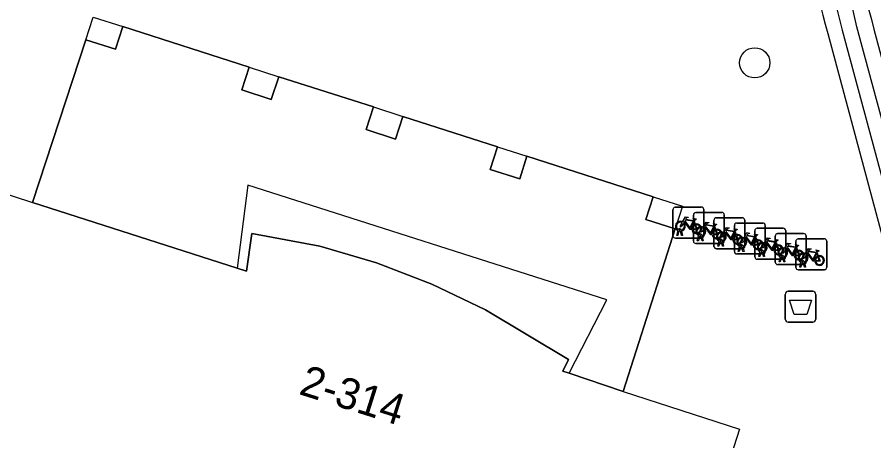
# Model space of a CAD drawing. Extents: x 160676 to 161153, y 383244 to 383713.
# Drawn here: x 161050.01 to 161077.72, y 383266.35 to 383280.05 of the extents above; entities that cross this region are included whole.
import ezdxf

# ---------------------------------------------------------------- set-up
doc = ezdxf.new("R2010")
doc.units = 0
for name, color, linetype in [('IMGEO_Afvalbak', 7, 'Continuous'), ('IMGEO_Boom', 7, 'Continuous'), ('IMGEO_Fietsenrek', 7, 'Continuous'), ('IMGEO_Pand', 7, 'Continuous'), ('IMGEO_Pand_nummerreeks', 7, 'Continuous'), ('IMGEO_Pand_overbouw', 7, 'Continuous'), ('IMGEO_Voetpad_open', 7, 'Continuous')]:
    doc.layers.add(name, color=color, linetype=linetype)

msp = doc.modelspace()

# ---------------------------------------------------------------- linework, layer by layer
at = {"layer": 'IMGEO_Afvalbak'}
for p, q in [((161074.848, 383270.288), (161074.848, 383271.088)), ((161074.848, 383271.088), (161074.848, 383270.288)), ((161074.948, 383271.188), (161075.738, 383271.188)), ((161075.738, 383271.188), (161074.948, 383271.188)), ((161075.838, 383271.088), (161075.838, 383270.288)), ((161075.838, 383270.288), (161075.838, 383271.088)), ((161075.738, 383270.188), (161074.948, 383270.188)), ((161074.948, 383270.188), (161075.738, 383270.188))]:
    msp.add_line(p, q, dxfattribs=at)
msp.add_lwpolyline([(161074.991, 383270.902), (161075.695, 383270.902), (161075.546, 383270.432), (161075.14, 383270.432), (161074.991, 383270.902)], dxfattribs=at)
for centre, start, end in [((161074.948, 383271.088), 90, 180), ((161074.948, 383271.088), 90, 180), ((161075.738, 383271.088), 0, 90), ((161075.738, 383271.088), 360, 90), ((161074.948, 383270.288), 180, 270), ((161074.948, 383270.288), 180, 270), ((161075.738, 383270.288), 270, 0), ((161075.738, 383270.288), 270, 0)]:
    msp.add_arc(centre, 0.1, start, end, dxfattribs=at)
at = {"layer": 'IMGEO_Boom'}
msp.add_circle((161073.864, 383278.575), 0.489, dxfattribs=at)
at = {"layer": 'IMGEO_Fietsenrek'}
for p, q in [((161071.219, 383272.982), (161071.219, 383273.823)), ((161071.219, 383273.823), (161071.219, 383272.982)), ((161071.294, 383273.907), (161072.135, 383273.907)), ((161072.135, 383273.907), (161071.294, 383273.907)), ((161072.219, 383273.832), (161072.219, 383272.991)), ((161072.219, 383272.991), (161072.219, 383273.832)), ((161071.881, 383272.811), (161071.881, 383273.652)), ((161071.881, 383273.652), (161071.881, 383272.811)), ((161071.956, 383273.736), (161072.797, 383273.736)), ((161072.797, 383273.736), (161071.956, 383273.736)), ((161072.618, 383273.566), (161073.459, 383273.566)), ((161073.459, 383273.566), (161072.618, 383273.566)), ((161072.881, 383273.661), (161072.881, 383272.82)), ((161072.881, 383272.82), (161072.881, 383273.661)), ((161071.906, 383273.456), (161071.942, 383273.361)), ((161072.543, 383272.641), (161072.543, 383273.482)), ((161072.543, 383273.482), (161072.543, 383272.641)), ((161072.568, 383273.285), (161072.604, 383273.19)), ((161073.205, 383272.47), (161073.205, 383273.311)), ((161073.205, 383273.311), (161073.205, 383272.47)), ((161073.28, 383273.395), (161074.121, 383273.395)), ((161074.121, 383273.395), (161073.28, 383273.395)), ((161073.543, 383273.491), (161073.543, 383272.65)), ((161073.543, 383272.65), (161073.543, 383273.491)), ((161074.205, 383273.32), (161074.205, 383272.479)), ((161074.205, 383272.479), (161074.205, 383273.32)), ((161071.346, 383272.991), (161071.385, 383273.151)), ((161071.38, 383272.991), (161071.346, 383272.991)), ((161071.415, 383273.139), (161071.38, 383272.991)), ((161071.457, 383273.163), (161071.456, 383273.167)), ((161071.498, 383272.991), (161071.464, 383273.133)), ((161071.488, 383273.174), (161071.489, 383273.167)), ((161071.496, 383273.137), (161071.531, 383272.991)), ((161071.531, 383272.991), (161071.498, 383272.991)), ((161072.008, 383272.82), (161072.047, 383272.98)), ((161072.077, 383272.968), (161072.042, 383272.82)), ((161072.119, 383272.992), (161072.118, 383272.996)), ((161072.15, 383273.003), (161072.151, 383272.996)), ((161073.23, 383273.115), (161073.266, 383273.02)), ((161073.867, 383272.3), (161073.867, 383273.141)), ((161073.867, 383273.141), (161073.867, 383272.3)), ((161073.942, 383273.225), (161074.783, 383273.225)), ((161074.783, 383273.225), (161073.942, 383273.225)), ((161074.529, 383272.129), (161074.529, 383272.97)), ((161074.529, 383272.97), (161074.529, 383272.129)), ((161074.604, 383273.054), (161075.445, 383273.054)), ((161075.445, 383273.054), (161074.604, 383273.054)), ((161074.867, 383273.15), (161074.867, 383272.309)), ((161074.867, 383272.309), (161074.867, 383273.15)), ((161075.529, 383272.979), (161075.529, 383272.138)), ((161075.529, 383272.138), (161075.529, 383272.979)), ((161072.144, 383272.907), (161071.303, 383272.907)), ((161071.303, 383272.907), (161072.144, 383272.907)), ((161072.806, 383272.736), (161071.965, 383272.736)), ((161071.965, 383272.736), (161072.806, 383272.736)), ((161072.042, 383272.82), (161072.008, 383272.82)), ((161072.16, 383272.82), (161072.126, 383272.962)), ((161072.158, 383272.966), (161072.193, 383272.82)), ((161072.193, 383272.82), (161072.16, 383272.82)), ((161072.67, 383272.65), (161072.709, 383272.81)), ((161072.739, 383272.798), (161072.704, 383272.65)), ((161072.781, 383272.822), (161072.78, 383272.826)), ((161072.822, 383272.65), (161072.788, 383272.792)), ((161072.812, 383272.833), (161072.813, 383272.826)), ((161072.82, 383272.796), (161072.855, 383272.65)), ((161073.892, 383272.944), (161073.928, 383272.849)), ((161074.554, 383272.774), (161074.59, 383272.679)), ((161075.191, 383271.958), (161075.191, 383272.799)), ((161075.191, 383272.799), (161075.191, 383271.958)), ((161075.266, 383272.883), (161076.107, 383272.883)), ((161076.107, 383272.883), (161075.266, 383272.883)), ((161076.191, 383272.808), (161076.191, 383271.967)), ((161076.191, 383271.967), (161076.191, 383272.808)), ((161073.468, 383272.566), (161072.627, 383272.566)), ((161072.627, 383272.566), (161073.468, 383272.566)), ((161072.704, 383272.65), (161072.67, 383272.65)), ((161072.855, 383272.65), (161072.822, 383272.65)), ((161073.332, 383272.479), (161073.371, 383272.639)), ((161073.366, 383272.479), (161073.332, 383272.479)), ((161073.401, 383272.627), (161073.366, 383272.479)), ((161073.443, 383272.651), (161073.442, 383272.655)), ((161073.484, 383272.479), (161073.45, 383272.621)), ((161073.474, 383272.662), (161073.475, 383272.655)), ((161073.482, 383272.625), (161073.517, 383272.479)), ((161073.517, 383272.479), (161073.484, 383272.479)), ((161073.994, 383272.309), (161074.033, 383272.469)), ((161074.063, 383272.457), (161074.028, 383272.309)), ((161074.105, 383272.481), (161074.104, 383272.485)), ((161074.146, 383272.309), (161074.112, 383272.451)), ((161074.136, 383272.492), (161074.137, 383272.485)), ((161074.144, 383272.455), (161074.179, 383272.309)), ((161075.216, 383272.603), (161075.252, 383272.508)), ((161075.878, 383272.432), (161075.914, 383272.337)), ((161074.13, 383272.395), (161073.289, 383272.395)), ((161073.289, 383272.395), (161074.13, 383272.395)), ((161074.792, 383272.225), (161073.951, 383272.225)), ((161073.951, 383272.225), (161074.792, 383272.225)), ((161074.028, 383272.309), (161073.994, 383272.309)), ((161074.179, 383272.309), (161074.146, 383272.309)), ((161074.656, 383272.138), (161074.695, 383272.298)), ((161074.69, 383272.138), (161074.656, 383272.138)), ((161074.725, 383272.286), (161074.69, 383272.138)), ((161074.767, 383272.31), (161074.766, 383272.314)), ((161074.808, 383272.138), (161074.774, 383272.28)), ((161074.798, 383272.321), (161074.799, 383272.314)), ((161074.806, 383272.284), (161074.841, 383272.138)), ((161074.841, 383272.138), (161074.808, 383272.138)), ((161075.429, 383272.139), (161075.428, 383272.143)), ((161075.46, 383272.15), (161075.461, 383272.143)), ((161075.454, 383272.054), (161074.613, 383272.054)), ((161074.613, 383272.054), (161075.454, 383272.054)), ((161076.116, 383271.883), (161075.275, 383271.883)), ((161075.275, 383271.883), (161076.116, 383271.883)), ((161075.318, 383271.967), (161075.357, 383272.127)), ((161075.352, 383271.967), (161075.318, 383271.967)), ((161075.387, 383272.115), (161075.352, 383271.967)), ((161075.47, 383271.967), (161075.436, 383272.109)), ((161075.468, 383272.113), (161075.503, 383271.967)), ((161075.503, 383271.967), (161075.47, 383271.967))]:
    msp.add_line(p, q, dxfattribs=at)
for points in [[(161071.532, 383273.433), (161071.627, 383273.597), (161071.713, 383273.583), (161071.715, 383273.574), (161071.659, 383273.563), (161071.632, 383273.518), (161071.888, 383273.477)], [(161071.888, 383273.477), (161071.913, 383273.526), (161071.907, 383273.53), (161071.884, 383273.534), (161071.872, 383273.541), (161071.871, 383273.544), (161071.873, 383273.549), (161071.968, 383273.534), (161071.97, 383273.524), (161071.96, 383273.511), (161071.948, 383273.505), (161071.934, 383273.511), (161071.906, 383273.456)], [(161071.553, 383273.381), (161071.501, 383273.291), (161071.461, 383273.266), (161071.462, 383273.313), (161071.517, 383273.407)], [(161071.828, 383273.189), (161071.778, 383273.189), (161071.587, 383273.44), (161071.568, 383273.408)], [(161071.875, 383273.452), (161071.618, 383273.493), (161071.601, 383273.464), (161071.768, 383273.244), (161071.875, 383273.452)], [(161071.923, 383273.354), (161071.893, 383273.431), (161071.784, 383273.213), (161071.827, 383273.213)], [(161071.857, 383273.213), (161071.977, 383273.212), (161071.933, 383273.326)], [(161071.953, 383273.333), (161072.008, 383273.188), (161071.858, 383273.188)], [(161072.194, 383273.262), (161072.289, 383273.426), (161072.375, 383273.412), (161072.377, 383273.403), (161072.321, 383273.392), (161072.294, 383273.347), (161072.55, 383273.306)], [(161072.49, 383273.018), (161072.44, 383273.018), (161072.249, 383273.269), (161072.23, 383273.237)], [(161072.537, 383273.281), (161072.28, 383273.322), (161072.263, 383273.293), (161072.43, 383273.073), (161072.537, 383273.281)], [(161072.585, 383273.183), (161072.555, 383273.26), (161072.446, 383273.042), (161072.489, 383273.042)], [(161072.55, 383273.306), (161072.575, 383273.355), (161072.569, 383273.359), (161072.546, 383273.363), (161072.534, 383273.37), (161072.533, 383273.373), (161072.535, 383273.378), (161072.63, 383273.363), (161072.632, 383273.353), (161072.622, 383273.34), (161072.61, 383273.334), (161072.596, 383273.34), (161072.568, 383273.285)], [(161072.856, 383273.092), (161072.951, 383273.256), (161073.037, 383273.242), (161073.039, 383273.233), (161072.983, 383273.222), (161072.956, 383273.177), (161073.212, 383273.136)], [(161072.215, 383273.21), (161072.163, 383273.12), (161072.123, 383273.095), (161072.124, 383273.142), (161072.179, 383273.236)], [(161072.519, 383273.042), (161072.639, 383273.041), (161072.595, 383273.155)], [(161072.615, 383273.162), (161072.67, 383273.017), (161072.52, 383273.017)], [(161072.877, 383273.04), (161072.825, 383272.95), (161072.785, 383272.925), (161072.786, 383272.972), (161072.841, 383273.066)], [(161073.152, 383272.848), (161073.102, 383272.848), (161072.911, 383273.099), (161072.892, 383273.067)], [(161073.199, 383273.111), (161072.942, 383273.152), (161072.925, 383273.123), (161073.092, 383272.903), (161073.199, 383273.111)], [(161073.247, 383273.013), (161073.217, 383273.09), (161073.108, 383272.872), (161073.151, 383272.872)], [(161073.181, 383272.872), (161073.301, 383272.871), (161073.257, 383272.985)], [(161073.277, 383272.992), (161073.332, 383272.847), (161073.182, 383272.847)], [(161073.212, 383273.136), (161073.237, 383273.185), (161073.231, 383273.189), (161073.208, 383273.193), (161073.196, 383273.2), (161073.195, 383273.203), (161073.197, 383273.208), (161073.292, 383273.193), (161073.294, 383273.183), (161073.284, 383273.17), (161073.272, 383273.164), (161073.258, 383273.17), (161073.23, 383273.115)], [(161073.518, 383272.921), (161073.613, 383273.085), (161073.699, 383273.071), (161073.701, 383273.062), (161073.645, 383273.051), (161073.618, 383273.006), (161073.874, 383272.965)], [(161073.861, 383272.94), (161073.604, 383272.981), (161073.587, 383272.952), (161073.754, 383272.732), (161073.861, 383272.94)], [(161073.874, 383272.965), (161073.899, 383273.014), (161073.893, 383273.018), (161073.87, 383273.022), (161073.858, 383273.029), (161073.857, 383273.032), (161073.859, 383273.037), (161073.954, 383273.022), (161073.956, 383273.012), (161073.946, 383272.999), (161073.934, 383272.993), (161073.92, 383272.999), (161073.892, 383272.944)], [(161073.539, 383272.869), (161073.487, 383272.779), (161073.447, 383272.754), (161073.448, 383272.801), (161073.503, 383272.895)], [(161073.814, 383272.677), (161073.764, 383272.677), (161073.573, 383272.928), (161073.554, 383272.896)], [(161073.909, 383272.842), (161073.879, 383272.919), (161073.77, 383272.701), (161073.813, 383272.701)], [(161073.843, 383272.701), (161073.963, 383272.7), (161073.919, 383272.814)], [(161073.939, 383272.821), (161073.994, 383272.676), (161073.844, 383272.676)], [(161074.201, 383272.699), (161074.149, 383272.609), (161074.109, 383272.584), (161074.11, 383272.631), (161074.165, 383272.725)], [(161074.18, 383272.751), (161074.275, 383272.915), (161074.361, 383272.901), (161074.363, 383272.892), (161074.307, 383272.881), (161074.28, 383272.836), (161074.536, 383272.795)], [(161074.476, 383272.507), (161074.426, 383272.507), (161074.235, 383272.758), (161074.216, 383272.726)], [(161074.523, 383272.77), (161074.266, 383272.811), (161074.249, 383272.782), (161074.416, 383272.562), (161074.523, 383272.77)], [(161074.571, 383272.672), (161074.541, 383272.749), (161074.432, 383272.531), (161074.475, 383272.531)], [(161074.536, 383272.795), (161074.561, 383272.844), (161074.555, 383272.848), (161074.532, 383272.852), (161074.52, 383272.859), (161074.519, 383272.862), (161074.521, 383272.867), (161074.616, 383272.852), (161074.618, 383272.842), (161074.608, 383272.829), (161074.596, 383272.823), (161074.582, 383272.829), (161074.554, 383272.774)], [(161074.842, 383272.58), (161074.937, 383272.744), (161075.023, 383272.73), (161075.025, 383272.721), (161074.969, 383272.71), (161074.942, 383272.665), (161075.198, 383272.624)], [(161075.198, 383272.624), (161075.223, 383272.673), (161075.217, 383272.677), (161075.194, 383272.681), (161075.182, 383272.688), (161075.181, 383272.691), (161075.183, 383272.696), (161075.278, 383272.681), (161075.28, 383272.671), (161075.27, 383272.658), (161075.258, 383272.652), (161075.244, 383272.658), (161075.216, 383272.603)], [(161074.505, 383272.531), (161074.625, 383272.53), (161074.581, 383272.644)], [(161074.601, 383272.651), (161074.656, 383272.506), (161074.506, 383272.506)], [(161074.863, 383272.528), (161074.811, 383272.438), (161074.771, 383272.413), (161074.772, 383272.46), (161074.827, 383272.554)], [(161075.138, 383272.336), (161075.088, 383272.336), (161074.897, 383272.587), (161074.878, 383272.555)], [(161075.185, 383272.599), (161074.928, 383272.64), (161074.911, 383272.611), (161075.078, 383272.391), (161075.185, 383272.599)], [(161075.233, 383272.501), (161075.203, 383272.578), (161075.094, 383272.36), (161075.137, 383272.36)], [(161075.167, 383272.36), (161075.287, 383272.359), (161075.243, 383272.473)], [(161075.263, 383272.48), (161075.318, 383272.335), (161075.168, 383272.335)], [(161075.504, 383272.409), (161075.599, 383272.573), (161075.685, 383272.559), (161075.687, 383272.55), (161075.631, 383272.539), (161075.604, 383272.494), (161075.86, 383272.453)], [(161075.8, 383272.165), (161075.75, 383272.165), (161075.559, 383272.416), (161075.54, 383272.384)], [(161075.847, 383272.428), (161075.59, 383272.469), (161075.573, 383272.44), (161075.74, 383272.22), (161075.847, 383272.428)], [(161075.86, 383272.453), (161075.885, 383272.502), (161075.879, 383272.506), (161075.856, 383272.51), (161075.844, 383272.517), (161075.843, 383272.52), (161075.845, 383272.525), (161075.94, 383272.51), (161075.942, 383272.5), (161075.932, 383272.487), (161075.92, 383272.481), (161075.906, 383272.487), (161075.878, 383272.432)], [(161075.525, 383272.357), (161075.473, 383272.267), (161075.433, 383272.242), (161075.434, 383272.289), (161075.489, 383272.383)], [(161075.895, 383272.33), (161075.865, 383272.407), (161075.756, 383272.189), (161075.799, 383272.189)], [(161075.829, 383272.189), (161075.949, 383272.188), (161075.905, 383272.302)], [(161075.925, 383272.309), (161075.98, 383272.164), (161075.83, 383272.164)]]:
    msp.add_lwpolyline(points, dxfattribs=at)
for centre, radius, start, end in [((161071.297, 383273.829), 0.0779, 92.4484, 184.2845), ((161071.297, 383273.829), 0.0779, 92.4484, 184.2845), ((161072.141, 383273.829), 0.0779, 2.4484, 94.2845), ((161072.141, 383273.829), 0.0779, 2.4484, 94.2845), ((161071.959, 383273.658), 0.0779, 92.4484, 184.2845), ((161071.959, 383273.658), 0.0779, 92.4484, 184.2845), ((161072.621, 383273.488), 0.0779, 92.4484, 184.2845), ((161072.621, 383273.488), 0.0779, 92.4484, 184.2845), ((161072.803, 383273.658), 0.0779, 2.4484, 94.2845), ((161072.803, 383273.658), 0.0779, 2.4484, 94.2845), ((161073.465, 383273.488), 0.0779, 2.4484, 94.2845), ((161073.465, 383273.488), 0.0779, 2.4484, 94.2845), ((161071.459, 383273.292), 0.159, 62.6766, 242.1369), ((161071.459, 383273.292), 0.129, 63.3192, 238.903), ((161071.459, 383273.292), 0.129, 283.6043, 43.4302), ((161071.459, 383273.292), 0.159, 283.5766, 46.6042), ((161071.986, 383273.208), 0.159, 113.3408, 178.3217), ((161071.986, 383273.208), 0.159, 187.0065, 105.7708), ((161071.986, 383273.208), 0.129, 113.923, 177.9556), ((161071.986, 383273.208), 0.129, 188.6715, 104.5883), ((161072.121, 383273.121), 0.159, 62.6766, 242.1369), ((161072.121, 383273.121), 0.129, 63.3192, 238.903), ((161073.283, 383273.317), 0.0779, 92.4484, 184.2845), ((161073.283, 383273.317), 0.0779, 92.4484, 184.2845), ((161074.127, 383273.317), 0.0779, 2.4484, 94.2845), ((161074.127, 383273.317), 0.0779, 2.4484, 94.2845), ((161071.297, 383272.985), 0.0779, 182.4484, 274.2845), ((161071.297, 383272.985), 0.0779, 182.4484, 274.2845), ((161071.439, 383273.163), 0.0499, 12.8025, 158.6934), ((161071.459, 383273.292), 0.159, 253.9967, 271.7867), ((161071.439, 383273.163), 0.0174, 12.8025, 163.4502), ((161071.459, 383273.292), 0.129, 253.415, 269.0204), ((161072.101, 383272.992), 0.0499, 12.8025, 158.6934), ((161072.121, 383273.121), 0.159, 253.9967, 271.7867), ((161072.101, 383272.992), 0.0174, 12.8025, 163.4502), ((161072.121, 383273.121), 0.129, 253.415, 269.0204), ((161072.141, 383272.985), 0.0779, 272.4484, 4.2845), ((161072.141, 383272.985), 0.0779, 272.4484, 4.2845), ((161072.121, 383273.121), 0.129, 283.6043, 43.4302), ((161072.121, 383273.121), 0.159, 283.5766, 46.6042), ((161072.648, 383273.037), 0.159, 113.3408, 178.3217), ((161072.648, 383273.037), 0.159, 187.0065, 105.7708), ((161072.648, 383273.037), 0.129, 113.923, 177.9556), ((161072.648, 383273.037), 0.129, 188.6715, 104.5883), ((161072.783, 383272.951), 0.159, 62.6766, 242.1369), ((161072.783, 383272.951), 0.129, 63.3192, 238.903), ((161072.783, 383272.951), 0.129, 283.6043, 43.4302), ((161072.783, 383272.951), 0.159, 283.5766, 46.6042), ((161073.31, 383272.867), 0.159, 113.3408, 178.3217), ((161073.31, 383272.867), 0.159, 187.0065, 105.7708), ((161073.31, 383272.867), 0.129, 113.923, 177.9556), ((161073.31, 383272.867), 0.129, 188.6715, 104.5883), ((161073.945, 383273.147), 0.0779, 92.4484, 184.2845), ((161073.945, 383273.147), 0.0779, 92.4484, 184.2845), ((161074.607, 383272.976), 0.0779, 92.4484, 184.2845), ((161074.607, 383272.976), 0.0779, 92.4484, 184.2845), ((161074.789, 383273.147), 0.0779, 2.4484, 94.2845), ((161074.789, 383273.147), 0.0779, 2.4484, 94.2845), ((161075.451, 383272.976), 0.0779, 2.4484, 94.2845), ((161075.451, 383272.976), 0.0779, 2.4484, 94.2845), ((161071.959, 383272.814), 0.0779, 182.4484, 274.2845), ((161071.959, 383272.814), 0.0779, 182.4484, 274.2845), ((161072.763, 383272.822), 0.0499, 12.8025, 158.6934), ((161072.783, 383272.951), 0.159, 253.9967, 271.7867), ((161072.763, 383272.822), 0.0174, 12.8025, 163.4502), ((161072.783, 383272.951), 0.129, 253.415, 269.0204), ((161072.803, 383272.814), 0.0779, 272.4484, 4.2845), ((161072.803, 383272.814), 0.0779, 272.4484, 4.2845), ((161073.445, 383272.78), 0.159, 62.6766, 242.1369), ((161073.445, 383272.78), 0.129, 63.3192, 238.903), ((161073.425, 383272.651), 0.0499, 12.8025, 158.6934), ((161073.445, 383272.78), 0.129, 283.6043, 43.4302), ((161073.445, 383272.78), 0.159, 283.5766, 46.6042), ((161073.972, 383272.696), 0.159, 113.3408, 178.3217), ((161073.972, 383272.696), 0.159, 187.0065, 105.7708), ((161073.972, 383272.696), 0.129, 113.923, 177.9556), ((161073.972, 383272.696), 0.129, 188.6715, 104.5883), ((161074.107, 383272.61), 0.159, 62.6766, 242.1369), ((161074.107, 383272.61), 0.129, 63.3192, 238.903), ((161074.107, 383272.61), 0.129, 283.6043, 43.4302), ((161074.107, 383272.61), 0.159, 283.5766, 46.6042), ((161075.269, 383272.805), 0.0779, 92.4484, 184.2845), ((161075.269, 383272.805), 0.0779, 92.4484, 184.2845), ((161076.113, 383272.805), 0.0779, 2.4484, 94.2845), ((161076.113, 383272.805), 0.0779, 2.4484, 94.2845), ((161072.621, 383272.644), 0.0779, 182.4484, 274.2845), ((161072.621, 383272.644), 0.0779, 182.4484, 274.2845), ((161073.283, 383272.473), 0.0779, 182.4484, 274.2845), ((161073.283, 383272.473), 0.0779, 182.4484, 274.2845), ((161073.445, 383272.78), 0.159, 253.9967, 271.7867), ((161073.425, 383272.651), 0.0174, 12.8025, 163.4502), ((161073.445, 383272.78), 0.129, 253.415, 269.0204), ((161073.465, 383272.644), 0.0779, 272.4484, 4.2845), ((161073.465, 383272.644), 0.0779, 272.4484, 4.2845), ((161074.087, 383272.481), 0.0499, 12.8025, 158.6934), ((161074.107, 383272.61), 0.159, 253.9967, 271.7867), ((161074.087, 383272.481), 0.0174, 12.8025, 163.4502), ((161074.107, 383272.61), 0.129, 253.415, 269.0204), ((161074.127, 383272.473), 0.0779, 272.4484, 4.2845), ((161074.127, 383272.473), 0.0779, 272.4484, 4.2845), ((161074.634, 383272.526), 0.159, 113.3408, 178.3217), ((161074.634, 383272.526), 0.159, 187.0065, 105.7708), ((161074.634, 383272.526), 0.129, 113.923, 177.9556), ((161074.634, 383272.526), 0.129, 188.6715, 104.5883), ((161074.769, 383272.439), 0.159, 62.6766, 242.1369), ((161074.769, 383272.439), 0.129, 63.3192, 238.903), ((161074.769, 383272.439), 0.129, 283.6043, 43.4302), ((161074.769, 383272.439), 0.159, 283.5766, 46.6042), ((161075.296, 383272.355), 0.159, 113.3408, 178.3217), ((161075.296, 383272.355), 0.159, 187.0065, 105.7708), ((161075.296, 383272.355), 0.129, 113.923, 177.9556), ((161075.296, 383272.355), 0.129, 188.6715, 104.5883), ((161075.431, 383272.268), 0.159, 62.6766, 242.1369), ((161073.945, 383272.303), 0.0779, 182.4484, 274.2845), ((161073.945, 383272.303), 0.0779, 182.4484, 274.2845), ((161074.749, 383272.31), 0.0499, 12.8025, 158.6934), ((161074.769, 383272.439), 0.159, 253.9967, 271.7867), ((161074.749, 383272.31), 0.0174, 12.8025, 163.4502), ((161074.769, 383272.439), 0.129, 253.415, 269.0204), ((161074.789, 383272.303), 0.0779, 272.4484, 4.2845), ((161074.789, 383272.303), 0.0779, 272.4484, 4.2845), ((161075.431, 383272.268), 0.129, 63.3192, 238.903), ((161075.411, 383272.139), 0.0499, 12.8025, 158.6934), ((161075.411, 383272.139), 0.0174, 12.8025, 163.4502), ((161075.431, 383272.268), 0.129, 253.415, 269.0204), ((161075.451, 383272.132), 0.0779, 272.4484, 4.2845), ((161075.451, 383272.132), 0.0779, 272.4484, 4.2845), ((161075.431, 383272.268), 0.129, 283.6043, 43.4302), ((161075.431, 383272.268), 0.159, 283.5766, 46.6042), ((161075.958, 383272.184), 0.159, 113.3408, 178.3217), ((161075.958, 383272.184), 0.159, 187.0065, 105.7708), ((161075.958, 383272.184), 0.129, 113.923, 177.9556), ((161075.958, 383272.184), 0.129, 188.6715, 104.5883), ((161074.607, 383272.132), 0.0779, 182.4484, 274.2845), ((161074.607, 383272.132), 0.0779, 182.4484, 274.2845), ((161075.269, 383271.961), 0.0779, 182.4484, 274.2845), ((161075.269, 383271.961), 0.0779, 182.4484, 274.2845), ((161075.431, 383272.268), 0.159, 253.9967, 271.7867), ((161076.113, 383271.961), 0.0779, 272.4484, 4.2845), ((161076.113, 383271.961), 0.0779, 272.4484, 4.2845)]:
    msp.add_arc(centre, radius, start, end, dxfattribs=at)
at = {"layer": 'IMGEO_Pand'}
for points in [[(161052.237, 383279.314), (161052.469, 383280.048), (161053.428, 383279.746)], [(161052.237, 383279.314), (161053.197, 383279.012), (161053.428, 383279.746)], [(161057.514, 383278.438), (161057.275, 383277.706), (161058.232, 383277.394), (161058.471, 383278.126)], [(161057.514, 383278.438), (161058.471, 383278.126)], [(161061.533, 383277.149), (161061.299, 383276.415), (161062.253, 383276.112), (161062.487, 383276.845)], [(161061.533, 383277.149), (161062.487, 383276.845)], [(161065.546, 383275.857), (161065.312, 383275.123), (161066.264, 383274.82), (161066.498, 383275.553)], [(161065.546, 383275.857), (161066.498, 383275.553)], [(161032.166, 383264.31), (161032.058, 383264.449), (161039.76, 383273.019), (161045.452, 383271.189), (161046.75, 383275.284), (161050.512, 383274.064)], [(161070.58, 383274.242), (161070.344, 383273.509), (161071.295, 383273.203)], [(161070.58, 383274.242), (161071.531, 383273.936), (161071.295, 383273.203)], [(161057.128, 383271.933), (161050.512, 383274.064)], [(161067.865, 383268.536), (161067.656, 383268.607), (161067.844, 383268.982), (161065.162, 383270.588), (161063.428, 383271.422), (161061.633, 383272.104), (161059.807, 383272.649), (161057.601, 383273.057), (161057.429, 383271.836), (161057.128, 383271.933)], [(161069.61, 383267.947), (161067.865, 383268.536)], [(161069.61, 383267.947), (161073.371, 383266.726), (161072.053, 383262.631), (161080.925, 383259.783)]]:
    msp.add_lwpolyline(points, dxfattribs=at)
at = {"layer": 'IMGEO_Pand_overbouw'}
msp.add_lwpolyline([(161070.58, 383274.242), (161066.498, 383275.553), (161066.264, 383274.82), (161065.312, 383275.123), (161065.546, 383275.857), (161062.487, 383276.845), (161062.253, 383276.112), (161061.299, 383276.415), (161061.533, 383277.149), (161058.471, 383278.126), (161058.232, 383277.394), (161057.275, 383277.706), (161057.514, 383278.438), (161053.428, 383279.746), (161053.197, 383279.012), (161052.237, 383279.314), (161050.512, 383274.064), (161057.128, 383271.933), (161057.429, 383271.836), (161057.601, 383273.057), (161059.807, 383272.649), (161061.633, 383272.104), (161063.428, 383271.422), (161065.162, 383270.588), (161067.844, 383268.982), (161067.656, 383268.607), (161067.865, 383268.536), (161069.61, 383267.947), (161071.295, 383273.203), (161070.344, 383273.509)], close=True, dxfattribs=at)
at = {"layer": 'IMGEO_Voetpad_open'}
for points in [[(161082.212, 383261.104), (161077.165, 383279.743), (161075.006, 383289.36), (161073.766, 383296.688)], [(161053.428, 383279.746), (161057.514, 383278.438)], [(161076.688, 383279.636), (161081.826, 383260.612)], [(161077.716, 383279.668), (161082.664, 383261.245), (161082.212, 383261.104)], [(161076.223, 383279.522), (161081.284, 383260.673), (161081.314, 383260.141), (161081.343, 383259.61)], [(161050.512, 383274.064), (161052.237, 383279.314)], [(161058.471, 383278.126), (161061.533, 383277.149)], [(161062.487, 383276.845), (161065.546, 383275.857)], [(161066.498, 383275.553), (161070.58, 383274.242)], [(161067.865, 383268.536), (161069.078, 383270.911), (161057.469, 383274.62), (161057.128, 383271.933)], [(161071.295, 383273.203), (161069.61, 383267.947)]]:
    msp.add_lwpolyline(points, dxfattribs=at)
for centre, radius, start, end in [((161213.026, 383315.367), 139.94, 190.66657, 194.77963), ((161199.05, 383312.414), 127.154, 190.53092, 194.99139), ((161249.081, 383323.359), 177.851, 191.04477, 194.23151)]:
    msp.add_arc(centre, radius, start, end, dxfattribs=at)

# ---------------------------------------------------------------- texts
at = {"layer": 'IMGEO_Pand_nummerreeks'}
msp.add_text('2-314', height=1, rotation=342.4774, dxfattribs=at).set_placement((161059.089, 383267.872))

doc.saveas('drawing.dxf')
